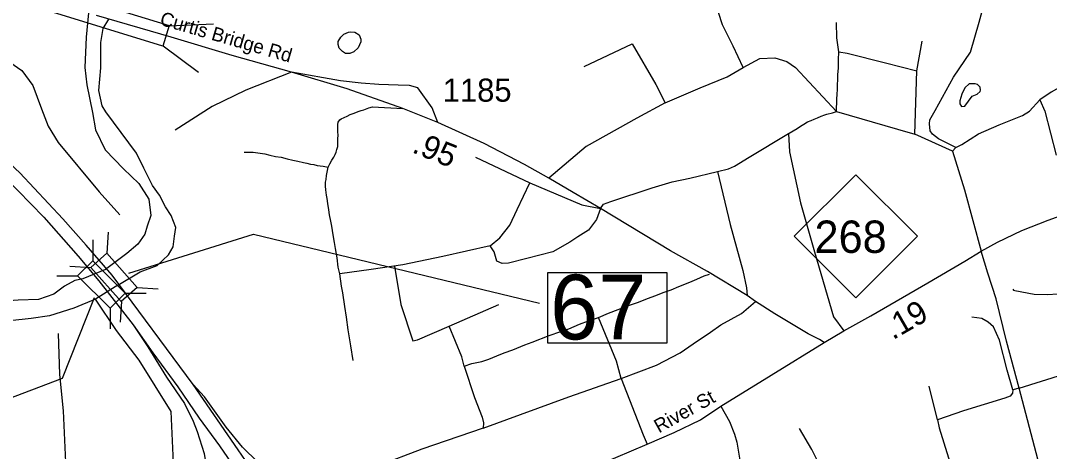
# Model space of a CAD drawing. Extents: x 1248224 to 1454986, y 825081 to 985870.
# Drawn here: x 1356695 to 1362257, y 877864 to 880196 of the extents above; entities that cross this region are included whole.
import ezdxf

# ---------------------------------------------------------------- set-up
doc = ezdxf.new("R2010")
doc.units = 0
for name, color, linetype in [('Exist Hydrographic Creek Single Shore', 7, 'Continuous'), ('Exist Hydrographic Misc Water Feature', 7, 'Continuous'), ('Exist Hydrographic River Shore', 7, 'Continuous'), ('Exist Road Non-System Type 51', 7, 'Continuous'), ('Exist Road Primary NC Attributed', 7, 'Continuous'), ('Exist Road Primary NC Label', 7, 'Continuous'), ('Exist Road Primary NC Mileage Hundredths English Label', 7, 'Continuous'), ('Exist Road Primary NC Shield CELL', 7, 'Continuous'), ('Exist Road Primary NC Shield Number Label', 7, 'Continuous'), ('Exist Road Primary US Divided Attributed', 7, 'Continuous'), ('Exist Road Primary US Ramp 1 Lane  Attributed', 7, 'Continuous'), ('Exist Road Primary US Structure Standard Bridge CELL', 7, 'Continuous'), ('Exist Road Primary US Structure Standard Bridge Number Label', 7, 'Continuous'), ('Exist Road Secondary Mileage Hundredths English Label', 7, 'Continuous'), ('Exist Road Secondary Structure Standard Bridge CELL', 7, 'Continuous'), ('Exist Road Secondary Type 51 Attributed', 7, 'Continuous'), ('Exist Road Secondary Type 51 Label', 7, 'Continuous'), ('Exist Road Secondary Type 51 Number Label', 7, 'Continuous')]:
    doc.layers.add(name, color=color, linetype=linetype)

msp = doc.modelspace()

# ---------------------------------------------------------------- linework, layer by layer
at = {"layer": 'Exist Hydrographic Creek Single Shore'}
msp.add_lwpolyline([(1356645.5, 875403.3), (1356724.7, 875732.1), (1356835.6, 876092.3), (1356945.7, 876266), (1356982.4, 876282.7), (1357242.7, 876770.2), (1357492.1, 877289), (1357536.9, 877445.2), (1357509.3, 878080.7), (1357335.7, 878357.8), (1357212.3, 878518.1), (1357099.3, 878689.1)], dxfattribs=at)
at = {"layer": 'Exist Hydrographic Misc Water Feature'}
for points in [[(1358467.4, 880133.1), (1358477, 880135.2), (1358500.9, 880132.6), (1358524.6, 880118.1), (1358534.1, 880095.8), (1358533.8, 880079.8), (1358519.1, 880048.1), (1358496.5, 880026.7), (1358474.4, 880017.2), (1358450.4, 880017.8), (1358434.6, 880028.1), (1358417, 880046.5), (1358411.4, 880066.6), (1358411.9, 880082.6), (1358426.3, 880106.3), (1358442.7, 880122), (1358467.4, 880133.1)], [(1361782, 879730.2), (1361800.2, 879733.2), (1361839.4, 879786.3), (1361865.6, 879797.7), (1361881.9, 879811.3), (1361884.1, 879819.3), (1361882.5, 879835.3), (1361868.8, 879849.6), (1361854.9, 879853.9), (1361822.9, 879852.6), (1361800.3, 879831.2), (1361783.6, 879797.6), (1361772.9, 879761.8), (1361772.5, 879745.8), (1361782, 879730.2)], [(1362058.3, 878743.3), (1362062.1, 878737.2), (1362070.1, 878735), (1362173.6, 878714.7), (1362245.6, 878713), (1362301.7, 878717.8)]]:
    msp.add_lwpolyline(points, dxfattribs=at)
at = {"layer": 'Exist Hydrographic River Shore'}
for points in [[(1357062.1, 880237.7), (1357048.9, 880105), (1357042.5, 879941.6), (1357052.1, 879848.6), (1357084.1, 879698), (1357100.1, 879605.1), (1357151.4, 879496.1), (1357250.6, 879393.5), (1357333.9, 879313.4), (1357388.3, 879230.1), (1357397.9, 879140.4), (1357378.7, 879082.7), (1357365.9, 879039.4), (1357328.6, 878986), (1357268.8, 878935.8), (1357153.5, 878848.2)], [(1357220.7, 878763.8), (1357340.3, 878835.4), (1357432.1, 878870.6), (1357494, 878927.3), (1357519.6, 878972.1), (1357526, 879028.7), (1357533.4, 879075.3), (1357508.8, 879140.5), (1357477.9, 879187.5), (1357444.8, 879250.5), (1357407.4, 879303.9), (1357360.5, 879397.9), (1357321, 879478), (1357155.8, 879701.4), (1357135.5, 879734.5), (1357117.4, 879817.9), (1357128, 879940.7), (1357129.1, 880077.4), (1357141.9, 880151.8), (1357172.4, 880203.6)], [(1357153.5, 878848.2), (1357031, 878799.2), (1356988.3, 878788.5), (1356931.7, 878758.6), (1356874.1, 878714.8), (1356791.9, 878687), (1356680.8, 878682.7), (1356604, 878677.4), (1356408.1, 878711.5), (1356320.6, 878743.6), (1356149.8, 878814.1), (1355995.4, 878857.7)], [(1357220.7, 878763.8), (1357099.3, 878689.1)], [(1357099.3, 878689.1), (1356982, 878639), (1356850.7, 878597.4), (1356751.4, 878584.6), (1356636.1, 878571.7)]]:
    msp.add_lwpolyline(points, dxfattribs=at)
at = {"layer": 'Exist Road Non-System Type 51'}
msp.add_line((1359011.1, 878542.3), (1359280.8, 878659.7), dxfattribs=at)
for points in [[(1360601, 879942.5), (1360546.8, 880057.3), (1360488.6, 880172.1), (1360468.1, 880238.6), (1360464, 880301.7), (1360476.3, 880349.3), (1360505, 880408.3), (1360572.2, 880479.7), (1360655.1, 880534.7), (1360737.9, 880566.6), (1360804.4, 880586.3), (1360866.7, 880617.5)], [(1361750, 879508.3), (1361656.3, 879556.1), (1361625, 879581.8), (1361612.2, 879598.4), (1361608.5, 879637), (1361610.3, 879659.1), (1361639.7, 879708.8), (1361739, 879889), (1361830.9, 880025.2), (1361876.9, 880187.1), (1361902.4, 880278.2), (1361913.5, 880294.8), (1361961.3, 880316.9), (1362051.3, 880329.7), (1362093.6, 880348.1), (1362108.3, 880366.5), (1362110.2, 880401.5), (1362154.3, 880456.7), (1362270.1, 880543.1)], [(1361117.4, 880026), (1361107.2, 880102.5), (1361105.4, 880185.3)], [(1359741.4, 879946.4), (1360001.6, 880069.2), (1360128.1, 879850), (1360178.7, 879750.1)], [(1361539.2, 879924.1), (1361568.6, 880084.1)], [(1356538.6, 880020.3), (1356636.7, 879969.8), (1356701.1, 879925), (1356760, 879843.6), (1356807.6, 879717.5), (1356844, 879624.9), (1356897.3, 879535.2), (1357118.6, 879268.8), (1357230.7, 879145.4)], [(1361105, 879704), (1361108.3, 879770), (1361108.9, 879798), (1361111.4, 879822), (1361113, 879902), (1361115.7, 879940), (1361116.6, 879984), (1361117.4, 880026)], [(1361117.4, 880026), (1361164.2, 880019.7), (1361370.1, 879966.4), (1361539.2, 879924.1)], [(1360601, 879942.5), (1360692, 879990), (1360771.6, 879994.1), (1360838, 879974.5), (1360883.9, 879942.5), (1361105, 879704)], [(1358159.5, 879916.1), (1357911.6, 879818.4), (1357729.5, 879731.5), (1357530.5, 879602.5)], [(1358949.5, 879643.5), (1358920.3, 879723.1), (1358841.9, 879832.4), (1358797.1, 879843.6), (1358735.4, 879846.4), (1358631.7, 879849.3), (1358536.5, 879857.7), (1358424.4, 879868.9), (1358159.5, 879916.1)], [(1360178.7, 879750.1), (1360368.5, 879832.5), (1360514, 879891.6), (1360601, 879942.5)], [(1361529.4, 879581.8), (1361539.2, 879924.1)], [(1362673.2, 879911.6), (1362501.2, 879869.3), (1362371.5, 879854.2), (1362320.2, 879839.2), (1362265.9, 879809), (1362205.6, 879766.7)], [(1358357.2, 879403.1), (1358365.6, 879420.9), (1358378, 879440.7), (1358388.3, 879456.5), (1358394.6, 879470.3), (1358400.9, 879484.2), (1358405.2, 879498.2), (1358409.5, 879514.1), (1358409.9, 879534.1), (1358410.4, 879558.1), (1358410.7, 879574.1), (1358409.1, 879596.1), (1358409.6, 879618.1), (1358409.9, 879634.1), (1358412.1, 879646.1), (1358420.4, 879657.9), (1358428.5, 879663.8), (1358444.7, 879671.5), (1358460.8, 879679.1), (1358477, 879686.8), (1358497.2, 879694.4), (1358519.4, 879704), (1358535.5, 879709.7), (1358549.6, 879713.4), (1358577.8, 879722.8), (1358597.9, 879728.4), (1358760.6, 879720)], [(1360178.7, 879750.1), (1360026.9, 879667.7), (1359752.3, 879515.1), (1359549.8, 879343.7)], [(1361733.1, 879489.3), (1361750, 879508.3), (1361783.2, 879525.2), (1361873.8, 879582.5), (1361985.4, 879630.8), (1362112.1, 879682.2), (1362148.3, 879706.3), (1362205.6, 879766.7)], [(1362205.6, 879766.7), (1362232.7, 879706.3), (1362293.1, 879467.8)], [(1360845.8, 879584.2), (1360850.5, 879587.1), (1360893, 879612.2), (1360911.3, 879623.9), (1360929.5, 879635.5), (1360949.7, 879647.1), (1360967.9, 879654.8), (1360984.1, 879662.5), (1361002.2, 879670.1), (1361022.4, 879677.7), (1361042.6, 879685.3), (1361052.7, 879689.1), (1361084.8, 879696.4), (1361105, 879704)], [(1361105, 879704), (1361436.3, 879607.7), (1361529.4, 879581.8)], [(1360462.7, 879378.9), (1360521.1, 879393.4), (1360554.1, 879408.1), (1360633.2, 879455.9), (1360845.8, 879584.2)], [(1360845.8, 879584.2), (1360851.9, 879485), (1360910.7, 879209), (1360986.1, 878944.1), (1361088.9, 878592.1), (1361145.9, 878516.7)], [(1361733.1, 879489.3), (1361529.4, 879581.8)], [(1357902.6, 879484.2), (1357952.6, 879483.2), (1357976.5, 879480.8), (1358014.4, 879474), (1358042.3, 879467.4), (1358072.2, 879460.8), (1358104.1, 879456.2), (1358136, 879447.5), (1358165.9, 879440.9), (1358193.8, 879434.4), (1358223.6, 879427.8), (1358241.6, 879423.4), (1358261.5, 879419), (1358279.5, 879416.6), (1358297.4, 879412.3), (1358331.3, 879407.6), (1358357.2, 879403.1)], [(1359154.6, 879455.9), (1359446.9, 879317.9)], [(1361733.1, 879489.3), (1361798.3, 879280.7), (1361887.6, 878948.2)], [(1358420.2, 878825.5), (1358412.4, 878861.6), (1358405.4, 878911.8), (1358396.4, 878962), (1358391, 878994.1), (1358383.9, 879036.3), (1358376.8, 879082.5), (1358371.4, 879110.6), (1358364.1, 879144.8), (1358360.6, 879170.8), (1358355.3, 879205), (1358351.8, 879233.1), (1358348.2, 879251.1), (1358344.7, 879279.2), (1358343.1, 879299.3), (1358343.6, 879321.3), (1358345.9, 879335.2), (1358348.3, 879357.2), (1358357.2, 879403.1)], [(1359829.6, 879179.6), (1359846.4, 879202.1), (1359885, 879216.8), (1360109.3, 879290.4), (1360217.8, 879323.5), (1360313.3, 879343.7), (1360462.7, 879378.9)], [(1360462.7, 879378.9), (1360530.7, 879092), (1360598.7, 878843.6), (1360618.9, 878749.8), (1360622.6, 878707.5)], [(1359233.7, 878977.6), (1359285.1, 879019.9), (1359340.3, 879088), (1359378.9, 879172.6), (1359446.9, 879317.9)], [(1359446.9, 879317.9), (1359728.2, 879198.3), (1359829.6, 879179.6)], [(1359829.6, 879179.6), (1359809, 879119.2), (1359764.9, 879062.2), (1359707.9, 879025.4), (1359663.8, 878996), (1359571.9, 878944.5), (1359432.2, 878907.7), (1359332.9, 878883.8), (1359298, 878881.9), (1359268.6, 878894.8), (1359255.7, 878944.5), (1359233.7, 878977.6)], [(1359233.7, 878977.6), (1358978.2, 878919), (1358761.3, 878874.9), (1358590.4, 878849.1), (1358420.2, 878825.5)], [(1358715.9, 878867), (1358751.1, 878659.7), (1358815.6, 878462.2), (1358841, 878468), (1359011.1, 878542.3)], [(1358492.3, 878355.7), (1358479.9, 878436), (1358465.6, 878522.3), (1358457, 878590.5), (1358448.2, 878648.8), (1358437.6, 878723), (1358430.4, 878759.2), (1358420.2, 878825.5)], [(1359819.8, 878589.2), (1359872.3, 878612.1), (1359924.8, 878633.1), (1359975.2, 878652.1), (1360035.6, 878672.9), (1360084, 878691.9), (1360128.4, 878709), (1360168.7, 878724.2), (1360211.1, 878739.4), (1360253.4, 878756.6), (1360311.9, 878779.4), (1360350.3, 878796.6), (1360390.7, 878813.8), (1360418.9, 878823.3)], [(1359940.6, 878259.8), (1360131.7, 878331.5), (1360260.4, 878397.7), (1360330.3, 878447.4), (1360424, 878510), (1360481, 878548.6), (1360591.3, 878611.1), (1360668.5, 878675.5)], [(1359092.7, 878326), (1359134.9, 878340.7), (1359188.3, 878351.8), (1359226.9, 878362.9), (1359269.3, 878382.1), (1359309.6, 878397.3), (1359356, 878414.4), (1359420.6, 878441.1), (1359460.9, 878456.3), (1359551.7, 878492.5), (1359616.2, 878513.2), (1359658.5, 878528.4), (1359717, 878553.2), (1359765.4, 878570.2), (1359819.8, 878589.2)], [(1359940.6, 878259.8), (1359915.6, 878353.4), (1359819.8, 878589.2)], [(1362059.3, 878198.5), (1362027.7, 878304.5), (1361986.8, 878466.3), (1361955.2, 878538.8), (1361925.4, 878563), (1361892, 878583.5), (1361838.1, 878590.9)], [(1357028.4, 877409.1), (1356996.5, 877468.3), (1356970.7, 877562.1), (1356939.5, 877806.8), (1356926.6, 878084.6), (1356906.5, 878280.7), (1356899.4, 878501.9)], [(1359092.7, 878326), (1359079.8, 878375.7), (1359011.1, 878542.3)], [(1362092.8, 878207.5), (1362335.2, 878282.7), (1362496.9, 878334.8), (1362530.4, 878342.2), (1362576.8, 878351.5)], [(1359092.7, 878326), (1359147.8, 878156.8), (1359190.1, 878050.1), (1359197.4, 878018.8), (1359195.7, 877989.7)], [(1359195.7, 877989.7), (1359397.9, 878065.1), (1359659, 878160.8), (1359940.6, 878259.8)], [(1359940.6, 878259.8), (1360060.8, 877954.2), (1360082.9, 877904.6)], [(1361652.2, 878034.8), (1361605.8, 878217.1)], [(1362092.8, 878207.5), (1362059.3, 878198.5), (1362057.4, 878179.9), (1362044.4, 878163.1), (1362016.5, 878152), (1361791.6, 878085), (1361652.2, 878034.8)], [(1360480.7, 878109.6), (1360526.9, 878026.5), (1360554.7, 877957.7), (1360567.7, 877914.9), (1360593.8, 877753.1), (1360614.2, 877561.5), (1360621.6, 877502), (1360653.2, 877403.5)], [(1361652.2, 878034.8), (1361661.5, 877992.8), (1361735.8, 877749.2), (1361746.9, 877689.9)], [(1359195.7, 877989.7), (1358864.7, 877877.2), (1358627.9, 877786.4)], [(1361130.3, 877532.3), (1361104.3, 877614.2), (1361050.4, 877720.2), (1360972.4, 877874.5), (1360905.8, 877988.9)]]:
    msp.add_lwpolyline(points, dxfattribs=at)
at = {"layer": 'Exist Road Primary NC Attributed'}
for points in [[(1361887.6, 878948.2), (1361976.2, 878996.5), (1362107.6, 879059.3), (1362250.6, 879116.2), (1362365.5, 879156.9), (1362479.8, 879190.7), (1362730.8, 879262.3), (1362848.1, 879298.8), (1362985.6, 879334.6), (1363181.2, 879384.3), (1363263.4, 879405.4), (1363368, 879432.5), (1363557.2, 879470.2), (1363649.2, 879493.6), (1363837.5, 879549.1), (1364176.8, 879636.4), (1364476, 879718.2), (1364717.7, 879782.6)], [(1361038.5, 878454.3), (1361145.9, 878516.7), (1361290.7, 878597.6), (1361600.1, 878775.8), (1361800, 878894.1), (1361887.6, 878948.2)], [(1362432.4, 876891.2), (1362419.2, 876961.8), (1362392.7, 877078.8), (1362330.9, 877306.2), (1362302.2, 877412.2), (1362231.7, 877683.7), (1362194.1, 877822.8), (1362092.8, 878207.5), (1362024.4, 878461.4), (1361969.3, 878691), (1361923.1, 878829), (1361887.6, 878948.2)], [(1358609.3, 877237), (1358719.9, 877243.9), (1358796.2, 877256.9), (1358885.2, 877282.4), (1358925.9, 877299.2), (1358964.2, 877313), (1359103.7, 877380.9), (1359323.8, 877530.8), (1359520.3, 877660.6), (1359666.2, 877729.7), (1359913.2, 877832.2), (1360082.9, 877904.6), (1360227.3, 877967.4), (1360370.6, 878035.3), (1360480.7, 878109.6), (1360751.8, 878277.1), (1361038.5, 878454.3)]]:
    msp.add_lwpolyline(points, dxfattribs=at)
at = {"layer": 'Exist Road Primary NC Shield CELL'}
msp.add_lwpolyline([(1360877.5, 879028.3), (1361210.5, 879361.3), (1361543.5, 879028.3), (1361210.5, 878695.3)], close=True, dxfattribs=at)
at = {"layer": 'Exist Road Primary US Divided Attributed'}
for points in [[(1354960.3, 880560.4), (1355180, 880460.5), (1355340.1, 880378.5), (1355452.3, 880317.3), (1355627.5, 880197.4), (1355760.1, 880099.1), (1355912.5, 879976), (1356003.1, 879903.3), (1356266.8, 879665.7), (1356360.5, 879590.6), (1356610.3, 879347.6), (1356820.7, 879132.4), (1357006.4, 878920.3), (1357117.2, 878787.3)], [(1357190.4, 878817.5), (1357049.7, 878980.7), (1356922.8, 879123.1), (1356690.8, 879372.3), (1356446.3, 879599.9), (1356283.9, 879731.4), (1356194.1, 879805.7), (1356100.5, 879879.3), (1356058.8, 879920.3), (1355985.3, 879986.1), (1355842.9, 880104.5), (1355751.6, 880173.4), (1355655.7, 880246.9)], [(1357117.2, 878787.3), (1357303.4, 878548.8)], [(1357626.8, 878226.9), (1357190.4, 878817.5)], [(1357303.4, 878548.8), (1357410.2, 878397.1), (1357544.8, 878214.5), (1357660.8, 878044.2), (1357770.7, 877894.1), (1357913, 877686.7), (1358087.9, 877434.3), (1358171.3, 877320.7)], [(1358275.4, 877296.6), (1358214.7, 877383.3), (1358009, 877671.2), (1357871.3, 877873.9), (1357626.8, 878226.9)]]:
    msp.add_lwpolyline(points, dxfattribs=at)
at = {"layer": 'Exist Road Primary US Ramp 1 Lane  Attributed'}
for points in [[(1357303.4, 878548.8), (1357381.8, 878430), (1357482.9, 878267.1), (1357580.4, 878123.2), (1357626.8, 878028.7), (1357650, 877971.5), (1357687.1, 877853.8), (1357699.5, 877773.3), (1357710.4, 877629.4), (1357715, 877500.9), (1357711.9, 877420.4)], [(1358609.3, 877237), (1358569.8, 877317.1), (1358530.4, 877373.8), (1358507.4, 877399.8), (1358470, 877431), (1358381, 877493.5), (1358142.4, 877660.5), (1358033.1, 877744.8), (1357977, 877807.2), (1357894.3, 877886.8), (1357805.4, 877996), (1357688.4, 878159.9), (1357626.8, 878226.9)]]:
    msp.add_lwpolyline(points, dxfattribs=at)
at = {"layer": 'Exist Road Primary US Structure Standard Bridge CELL'}
for p, q in [((1357085, 879009.8), (1357084.9, 878896.6)), ((1357167.6, 879050), (1357160.9, 878937.1)), ((1356961.3, 878866.9), (1357074.3, 878860.2)), ((1356889.8, 878814.8), (1357003, 878814.8)), ((1357325.1, 878751.3), (1357438, 878744.6)), ((1357240.4, 878676.2), (1357233.7, 878563.2)), ((1357259.7, 878720.9), (1357372.9, 878720.8)), ((1357179.7, 878640.9), (1357179.6, 878527.7))]:
    msp.add_line(p, q, dxfattribs=at)
for points in [[(1357084.9, 878896.6), (1357260.1, 878721.3), (1357178.2, 878639.4), (1357003, 878814.8)], [(1357160.9, 878937.1), (1357325.5, 878751.7), (1357238.9, 878674.8), (1357074.3, 878860.2)]]:
    msp.add_lwpolyline(points, close=True, dxfattribs=at)
at = {"layer": 'Exist Road Primary US Structure Standard Bridge Number Label'}
for points in [[(1357279, 878829.2), (1357954.5, 879040.8), (1359500.7, 878666.4)], [(1357092.7, 878694.7), (1356918.7, 878259.8), (1355922.3, 877880.2)]]:
    msp.add_lwpolyline(points, dxfattribs=at)
msp.add_lwpolyline([(1359544.9, 878833.1), (1360189, 878833.1), (1360189, 878450.8), (1359544.9, 878450.8)], close=True, dxfattribs=at)
at = {"layer": 'Exist Road Secondary Structure Standard Bridge CELL'}
for p, q in [((1357498.4, 880167.8), (1357737.3, 880177.8)), ((1357465, 880059.7), (1357656.7, 879916.8))]:
    msp.add_line(p, q, dxfattribs=at)
msp.add_lwpolyline([(1356831.6, 880374.3), (1357498.5, 880168.4), (1357464.4, 880057.7), (1356797.4, 880263.6)], close=True, dxfattribs=at)
at = {"layer": 'Exist Road Secondary Type 51 Attributed'}
msp.add_lwpolyline([(1361038.5, 878454.3), (1361014.5, 878469.3), (1360953, 878500.8), (1360771.7, 878608.8), (1360668.5, 878675.5), (1360622.6, 878707.5), (1360407.7, 878837.9), (1360208.8, 878950.1), (1359829.6, 879179.6), (1359681.8, 879266), (1359549.8, 879343.7), (1359418, 879417.5), (1359201.3, 879531), (1358949.5, 879643.5), (1358760.6, 879720), (1358459.3, 879826.5), (1358159.5, 879916.1), (1357838.7, 880006.1), (1357509, 880105.1), (1357104.8, 880223.8)], dxfattribs=at)

# ---------------------------------------------------------------- texts
at = {"layer": 'Exist Road Primary NC Label'}
msp.add_text('River St', height=75, rotation=29.1239, dxfattribs=at).set_placement((1360145.6, 877961.7))
at = {"layer": 'Exist Road Primary NC Mileage Hundredths English Label'}
msp.add_text('.19', height=125, rotation=29.939, dxfattribs=at).set_placement((1361410.5, 878465.6))
at = {"layer": 'Exist Road Primary NC Shield Number Label'}
msp.add_text('268', height=175, dxfattribs=at).set_placement((1360986.6, 878938.6))
at = {"layer": 'Exist Road Primary US Structure Standard Bridge Number Label'}
msp.add_text('67', height=350, dxfattribs=at).set_placement((1359557.4, 878470.6))
at = {"layer": 'Exist Road Secondary Mileage Hundredths English Label'}
msp.add_text('.95', height=125, rotation=337.9479, dxfattribs=at).set_placement((1358805.2, 879484.5))
at = {"layer": 'Exist Road Secondary Type 51 Label'}
msp.add_text('Curtis Bridge Rd', height=75, rotation=343.728, dxfattribs=at).set_placement((1357442.8, 880174))
at = {"layer": 'Exist Road Secondary Type 51 Number Label'}
msp.add_text('1185', height=125, dxfattribs=at).set_placement((1358977.1, 879756.7))

doc.saveas('drawing.dxf')
